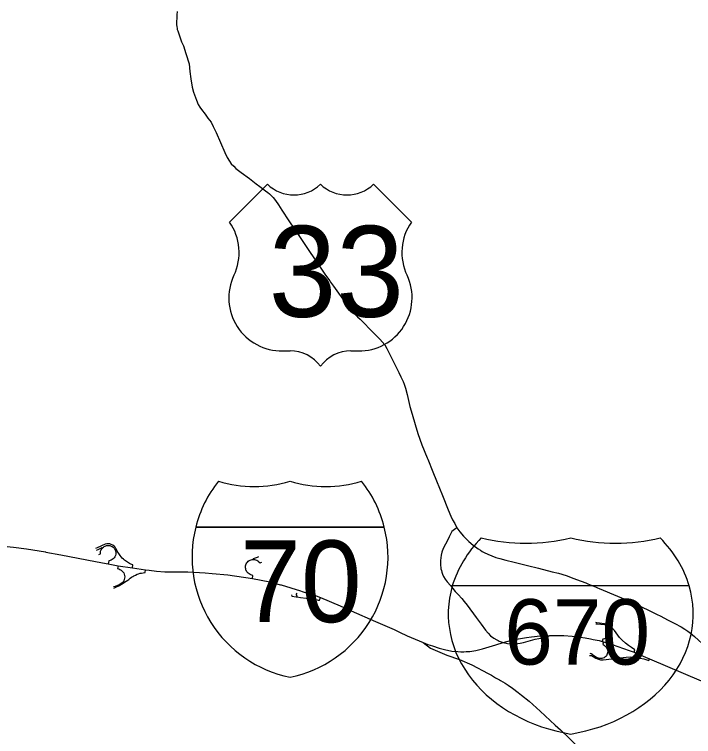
# Model space of a CAD drawing. Extents: x 0 to 34, y 0 to 22.
# Drawn here: x 4.266 to 5.228, y 17.132 to 18.155 of the extents above; entities that cross this region are included whole.
import ezdxf

# ---------------------------------------------------------------- set-up
doc = ezdxf.new("R2010")
doc.units = 0
for name, color, linetype in [('GM_X_Interchange_Ramps', 7, 'Continuous'), ('GM_X_Interstate_Route', 7, 'Continuous'), ('GM_X_Interstate_Shield', 7, 'Continuous'), ('GM_X_US_Route', 7, 'Continuous'), ('GM_X_US_Shield', 7, 'Continuous')]:
    doc.layers.add(name, color=color, linetype=linetype)

msp = doc.modelspace()

# ---------------------------------------------------------------- linework, layer by layer
at = {"layer": 'GM_X_Interchange_Ramps'}
for points in [[(4.4333, 17.3713), (4.434, 17.3754), (4.431, 17.3767), (4.4293, 17.3776), (4.4277, 17.3784), (4.4264, 17.3792), (4.4249, 17.3802), (4.4235, 17.3811), (4.4219, 17.3824), (4.4204, 17.3837), (4.4188, 17.3852), (4.4173, 17.3868), (4.4157, 17.3888), (4.4147, 17.3901), (4.4138, 17.3915), (4.4127, 17.3933), (4.4117, 17.395), (4.411, 17.3964), (4.4099, 17.3988), (4.4087, 17.4006), (4.4072, 17.4021), (4.4055, 17.4034), (4.4031, 17.4046), (4.401, 17.4052), (4.399, 17.4054), (4.3968, 17.4053), (4.3945, 17.4048), (4.3832, 17.3998), (4.3811, 17.3988)], [(4.3825, 17.3964), (4.3846, 17.3975), (4.3904, 17.4001), (4.3907, 17.3995)], [(4.3856, 17.3901), (4.3879, 17.3913), (4.3879, 17.3931), (4.3882, 17.3949), (4.389, 17.397), (4.3898, 17.3984), (4.3907, 17.3995), (4.3921, 17.4006), (4.3933, 17.4016), (4.3945, 17.4022), (4.3964, 17.4028), (4.3986, 17.4031), (4.401, 17.4029), (4.4029, 17.4022), (4.4044, 17.4015), (4.4059, 17.4004), (4.4072, 17.3991), (4.4084, 17.3972), (4.4092, 17.3952), (4.4096, 17.3932), (4.4096, 17.3909), (4.4091, 17.3888), (4.4084, 17.387), (4.4072, 17.3853), (4.4059, 17.3839), (4.4045, 17.3829), (4.403, 17.3821), (4.4015, 17.3816), (4.3996, 17.3813), (4.3989, 17.3768)], [(4.6044, 17.3832), (4.6045, 17.3844), (4.6103, 17.3866), (4.6123, 17.3875)], [(4.6031, 17.3561), (4.6037, 17.3606), (4.6024, 17.361), (4.6011, 17.3615), (4.5999, 17.362), (4.5984, 17.3628), (4.5973, 17.3636), (4.5963, 17.3645), (4.5953, 17.3657), (4.5946, 17.367), (4.594, 17.3682), (4.5936, 17.3697), (4.5934, 17.3711), (4.5933, 17.3726), (4.5935, 17.374), (4.5939, 17.3756), (4.5945, 17.377), (4.5953, 17.3784), (4.5961, 17.3795), (4.5972, 17.3806), (4.5985, 17.3815), (4.5999, 17.3822), (4.6015, 17.3828), (4.603, 17.3831), (4.6044, 17.3832), (4.6061, 17.383), (4.6076, 17.3827), (4.6092, 17.3821), (4.6106, 17.3812), (4.6118, 17.3803), (4.614, 17.3782), (4.6163, 17.3792)], [(4.4129, 17.3743), (4.4122, 17.3703), (4.414, 17.3697), (4.4156, 17.3691), (4.4172, 17.3682), (4.4184, 17.3673), (4.4197, 17.3659), (4.4209, 17.3641), (4.4216, 17.3624), (4.4221, 17.3604), (4.4223, 17.3587), (4.4221, 17.3567), (4.4216, 17.3549), (4.4209, 17.3531), (4.4199, 17.3516), (4.4187, 17.3502), (4.4172, 17.3492), (4.4153, 17.3479), (4.4086, 17.3451), (4.4064, 17.3442)], [(4.4071, 17.3427), (4.4087, 17.3435), (4.4148, 17.3464), (4.4179, 17.3484), (4.4202, 17.3497), (4.4221, 17.3508), (4.4244, 17.3523), (4.4265, 17.3537), (4.4282, 17.3549), (4.43, 17.3565), (4.4319, 17.3579), (4.4336, 17.359), (4.4354, 17.3601), (4.4374, 17.3611), (4.4399, 17.3622), (4.442, 17.363), (4.4441, 17.3636), (4.4462, 17.364), (4.4485, 17.3644), (4.4512, 17.3648), (4.4517, 17.3686)], [(4.6659, 17.3354), (4.6652, 17.3342), (4.6652, 17.3327), (4.6654, 17.3324), (4.6656, 17.332), (4.6659, 17.3317), (4.6662, 17.3314), (4.6661, 17.3303)], [(4.6585, 17.333), (4.6591, 17.3311), (4.665, 17.3304), (4.6661, 17.3303), (4.6713, 17.3293), (4.6793, 17.3284), (4.6815, 17.328), (4.6835, 17.3277), (4.6859, 17.3274), (4.688, 17.327), (4.6902, 17.3267), (4.6925, 17.3263), (4.6947, 17.326), (4.6964, 17.3257), (4.698, 17.3254), (4.6995, 17.3294)], [(5.0893, 17.2922), (5.0913, 17.2919), (5.1017, 17.291), (5.1034, 17.2908), (5.105, 17.2903), (5.1066, 17.2895), (5.108, 17.2884), (5.1091, 17.2872), (5.1099, 17.286), (5.1106, 17.2847), (5.111, 17.2831), (5.1113, 17.2814), (5.1112, 17.2801), (5.111, 17.2786), (5.1105, 17.2772), (5.1099, 17.276), (5.1092, 17.2748), (5.1082, 17.2737), (5.107, 17.2727), (5.1056, 17.2719), (5.1045, 17.2715), (5.1032, 17.2711), (5.102, 17.2708), (5.0993, 17.2704), (5.0984, 17.2671)], [(5.1437, 17.2517), (5.1449, 17.2552), (5.1399, 17.2585), (5.1356, 17.2614), (5.1317, 17.2646), (5.1268, 17.2691), (5.1231, 17.2727), (5.1158, 17.2824), (5.1114, 17.2878), (5.1078, 17.2903), (5.1046, 17.2917), (5.1019, 17.2922), (5.091, 17.2936), (5.0895, 17.2938)], [(5.1004, 17.2666), (5.0995, 17.263), (5.102, 17.2613), (5.103, 17.26), (5.104, 17.2591), (5.1048, 17.2579), (5.1056, 17.2565), (5.106, 17.2553), (5.1063, 17.254), (5.1064, 17.2526), (5.1062, 17.2509), (5.1058, 17.2493), (5.1053, 17.2482), (5.1046, 17.2469), (5.1036, 17.2458), (5.1024, 17.2447), (5.1011, 17.2439), (5.0996, 17.2433), (5.098, 17.2429), (5.0962, 17.2428), (5.0947, 17.243), (5.0934, 17.2433), (5.0907, 17.2443), (5.0869, 17.2466), (5.0851, 17.248), (5.0831, 17.2496), (5.0813, 17.2501)], [(5.0807, 17.2474), (5.0834, 17.2471), (5.0897, 17.2432), (5.0932, 17.2418), (5.0963, 17.2411), (5.1, 17.2411), (5.1326, 17.2447), (5.1381, 17.2451), (5.143, 17.2448), (5.1463, 17.2445), (5.1521, 17.2435), (5.1574, 17.2423), (5.1648, 17.2402), (5.1656, 17.2425)]]:
    msp.add_lwpolyline(points, dxfattribs=at)
at = {"layer": 'GM_X_Interstate_Route'}
for points in [[(4.2367, 17.4035), (4.2649, 17.4008), (4.2832, 17.3983), (4.3099, 17.3938), (4.3106, 17.3937)], [(4.3106, 17.3937), (4.3316, 17.3896), (4.3688, 17.3828), (4.3909, 17.3783)], [(4.3909, 17.3783), (4.3989, 17.3768), (4.4129, 17.3743), (4.4333, 17.3713), (4.4517, 17.3686), (4.457, 17.3678)], [(4.457, 17.3678), (4.4672, 17.3664), (4.4791, 17.3655), (4.5116, 17.3656), (4.5364, 17.3644), (4.546, 17.3635), (4.5682, 17.3615), (4.6031, 17.3561), (4.6276, 17.3513)], [(4.6276, 17.3513), (4.629, 17.351), (4.6321, 17.3502)], [(4.6321, 17.3502), (4.6431, 17.3474)], [(4.6431, 17.3474), (4.6437, 17.3473), (4.6576, 17.3429), (4.6711, 17.3387), (4.6738, 17.3379), (4.6765, 17.337), (4.6822, 17.3352)], [(4.6822, 17.3352), (4.691, 17.3325), (4.6995, 17.3294), (4.7274, 17.3177), (4.7432, 17.3104), (4.7773, 17.2952), (4.8038, 17.2838)], [(4.8038, 17.2838), (4.8117, 17.2804), (4.8221, 17.2751), (4.8335, 17.2702), (4.845, 17.2655)], [(4.9794, 17.2706), (4.9798, 17.2707), (4.9911, 17.2726), (4.9983, 17.2736), (5.0105, 17.2749), (5.0242, 17.2756)], [(5.0242, 17.2756), (5.0442, 17.2753), (5.0559, 17.2745), (5.0673, 17.273), (5.0743, 17.272), (5.0818, 17.2708), (5.0856, 17.2699), (5.0941, 17.2682), (5.0984, 17.2671), (5.1004, 17.2666), (5.1096, 17.2637)], [(4.845, 17.2655), (4.8556, 17.2577), (4.8783, 17.2475), (4.8963, 17.2417), (4.8965, 17.2416)], [(4.845, 17.2655), (4.8518, 17.2629), (4.8582, 17.2607), (4.8677, 17.2575), (4.875, 17.2555), (4.8855, 17.2535), (4.894, 17.2528), (4.8982, 17.2526), (4.9027, 17.2526), (4.9059, 17.2527), (4.9111, 17.253), (4.9196, 17.2544), (4.9291, 17.2565), (4.9386, 17.2595)], [(4.9386, 17.2595), (4.9477, 17.2623), (4.9581, 17.2657), (4.9707, 17.2687), (4.9794, 17.2706)], [(5.1096, 17.2637), (5.1127, 17.2628), (5.1368, 17.2544), (5.1437, 17.2517), (5.1534, 17.2477), (5.1599, 17.2449), (5.1656, 17.2425), (5.2387, 17.2115), (5.2547, 17.2046), (5.2604, 17.2023), (5.2647, 17.2007), (5.2707, 17.1988), (5.2748, 17.1978), (5.2794, 17.197), (5.284, 17.1964), (5.288, 17.1962), (5.2938, 17.1962), (5.2988, 17.1966), (5.3022, 17.197), (5.3055, 17.1976), (5.3092, 17.1985), (5.3118, 17.1992), (5.3154, 17.2004)], [(4.8965, 17.2416), (4.914, 17.2341), (4.9372, 17.2219), (4.9417, 17.2192)], [(4.9417, 17.2192), (4.9476, 17.2157), (4.9529, 17.2128), (4.9543, 17.212)], [(4.9543, 17.212), (4.961, 17.208), (4.9655, 17.2052), (4.9716, 17.2007), (4.9794, 17.195), (4.9844, 17.1908), (4.9949, 17.1825), (5.0105, 17.1683), (5.0318, 17.1484), (5.0395, 17.1419), (5.052, 17.1298), (5.0641, 17.1176), (5.0746, 17.1074), (5.0907, 17.0882), (5.0972, 17.0802), (5.104, 17.0714)]]:
    msp.add_lwpolyline(points, dxfattribs=at)
at = {"layer": 'GM_X_Interstate_Shield'}
for p, q in [((4.5229, 17.4289), (4.7899, 17.4289)), ((4.7899, 17.4289), (4.5229, 17.4289)), ((4.7899, 17.4289), (4.5229, 17.4289)), ((5.2218, 17.3457), (4.8862, 17.3457)), ((5.2218, 17.3457), (4.8862, 17.3457))]:
    msp.add_line(p, q, dxfattribs=at)
for centre, start, end in [((4.6911, 17.3864), 141.669, 165.8066), ((4.6057, 17.66), 253.0091, 286.9909), ((4.7071, 17.66), 253.0091, 286.9909), ((4.6217, 17.3864), 14.1934, 38.331), ((4.6911, 17.3864), 165.8066, 258.463), ((4.6217, 17.3864), 281.537, 14.1934)]:
    msp.add_arc(centre, 0.1735, start, end, dxfattribs=at)
for centre, start_param, end_param in [((5.0974, 17.306), 2.47259, 2.911027), ((4.9906, 17.5796), 4.415841, 5.008937), ((5.1174, 17.5796), 4.415841, 5.008937), ((5.0106, 17.306), 0.230566, 0.669003), ((5.0974, 17.306), 2.911027, 4.511031), ((5.0106, 17.306), 4.913747, 6.513751)]:
    msp.add_ellipse(centre, major_axis=(0.2169, 0), ratio=0.8, start_param=start_param, end_param=end_param, dxfattribs=at)
at = {"layer": 'GM_X_US_Route'}
for points in [[(4.4966, 18.1594), (4.4962, 18.1544), (4.4956, 18.1406), (4.496, 18.1379), (4.4964, 18.1351), (4.4968, 18.1336), (4.4973, 18.1319), (4.5027, 18.1165), (4.5054, 18.1105), (4.5088, 18.1), (4.5134, 18.0852), (4.5146, 18.0744), (4.5158, 18.0639), (4.5178, 18.052), (4.5199, 18.0451), (4.5238, 18.0338), (4.5265, 18.0274), (4.5286, 18.0238), (4.5309, 18.0203), (4.5361, 18.0137), (4.5401, 18.0084), (4.5445, 18.0024), (4.5477, 17.9964), (4.5516, 17.9881), (4.5641, 17.9596), (4.5675, 17.9523), (4.5705, 17.9473), (4.5732, 17.9437), (4.5766, 17.9403), (4.5799, 17.9369), (4.5871, 17.9313), (4.5989, 17.9226), (4.6086, 17.9153), (4.6137, 17.9114), (4.6219, 17.9052), (4.6252, 17.9027)], [(4.6252, 17.9027), (4.6272, 17.9012), (4.6299, 17.8987), (4.6326, 17.8958), (4.636, 17.8916), (4.6401, 17.8855), (4.6448, 17.8781)], [(4.6448, 17.8781), (4.6548, 17.8626), (4.6697, 17.8406), (4.6832, 17.8208)], [(4.6832, 17.8208), (4.6842, 17.8193), (4.6952, 17.8029), (4.7065, 17.786)], [(4.7065, 17.786), (4.7127, 17.7776), (4.7137, 17.7761)], [(4.7137, 17.7761), (4.718, 17.7701), (4.725, 17.7603), (4.7324, 17.7501), (4.7353, 17.7462)], [(4.7353, 17.7462), (4.7387, 17.7415), (4.7464, 17.7327), (4.752, 17.7269), (4.7557, 17.7234), (4.7591, 17.72), (4.7718, 17.7072), (4.7837, 17.6951), (4.7908, 17.6872), (4.7934, 17.6822), (4.7994, 17.6707), (4.8058, 17.6573), (4.8101, 17.6487), (4.8104, 17.6482)], [(4.8104, 17.6482), (4.8135, 17.642), (4.8166, 17.6354), (4.8183, 17.6313), (4.82, 17.6259), (4.8223, 17.6168), (4.8263, 17.5997), (4.8292, 17.5888), (4.8335, 17.5742), (4.8376, 17.5616), (4.8432, 17.5455), (4.8507, 17.5271), (4.8514, 17.5253)], [(4.8514, 17.5253), (4.8585, 17.5075), (4.864, 17.4944), (4.8723, 17.4738), (4.8806, 17.4534), (4.8843, 17.4445), (4.8867, 17.4395), (4.8896, 17.434), (4.8929, 17.4278)], [(4.8929, 17.4278), (4.8894, 17.4255), (4.8858, 17.4226), (4.8843, 17.4201), (4.8819, 17.4153)], [(4.8929, 17.4278), (4.897, 17.4224), (4.9021, 17.4163), (4.9097, 17.4085), (4.9157, 17.4034), (4.9227, 17.3983), (4.926, 17.3962), (4.9286, 17.3946), (4.9313, 17.3931), (4.9364, 17.3905), (4.9423, 17.3881), (4.9477, 17.3862), (4.9535, 17.3844), (4.9619, 17.3822), (4.9739, 17.3793), (4.9927, 17.3747), (5.0084, 17.3707), (5.0278, 17.3658), (5.0367, 17.3637), (5.0474, 17.3603), (5.0583, 17.3563), (5.0621, 17.3548), (5.0752, 17.3499), (5.0784, 17.3486), (5.09, 17.3438), (5.092, 17.343)], [(4.8819, 17.4153), (4.8798, 17.4111), (4.8735, 17.3985), (4.8716, 17.3935), (4.8704, 17.3893), (4.8698, 17.3853), (4.8693, 17.3817), (4.8693, 17.3776), (4.8695, 17.3746), (4.8699, 17.3719), (4.8702, 17.3697), (4.8708, 17.3674), (4.8715, 17.365), (4.8726, 17.3622), (4.874, 17.3592), (4.8761, 17.3554), (4.8789, 17.3515), (4.8836, 17.3462), (4.8905, 17.338), (4.8947, 17.3334), (4.8999, 17.3277), (4.9032, 17.3237)], [(5.092, 17.343), (5.0941, 17.3422)], [(5.0941, 17.3422), (5.1202, 17.3313), (5.1337, 17.3255), (5.1514, 17.3173), (5.1677, 17.3095), (5.1755, 17.3056)], [(4.9032, 17.3237), (4.9074, 17.3186), (4.92, 17.301), (4.9269, 17.2916), (4.9334, 17.2829), (4.9371, 17.2786), (4.9405, 17.2751), (4.9449, 17.2719), (4.9493, 17.2694), (4.951, 17.2684), (4.9528, 17.2676), (4.9581, 17.2657), (4.9642, 17.2642), (4.9692, 17.2636), (4.9723, 17.2636), (4.9759, 17.2637), (4.9823, 17.2647), (4.9873, 17.2657), (4.997, 17.2685), (5.0036, 17.2702), (5.0089, 17.2711), (5.0167, 17.2718), (5.0242, 17.2756)], [(5.1755, 17.3056), (5.1814, 17.3027), (5.1908, 17.2978), (5.2014, 17.2924), (5.2104, 17.2876), (5.2157, 17.2846), (5.22, 17.2816), (5.2234, 17.279), (5.2292, 17.2742), (5.2348, 17.2691), (5.2403, 17.2643), (5.2403, 17.2643)]]:
    msp.add_lwpolyline(points, dxfattribs=at)
at = {"layer": 'GM_X_US_Shield'}
for p, q in [((4.6244, 17.9147), (4.5707, 17.8611)), ((4.8284, 17.8611), (4.7747, 17.9147)), ((4.6459, 17.6785), (4.6566, 17.6785)), ((4.7425, 17.6785), (4.7532, 17.6785))]:
    msp.add_line(p, q, dxfattribs=at)
for centre, radius, start, end in [((4.662, 17.9531), 0.0537, 225.573, 314.427), ((4.7371, 17.9531), 0.0537, 225.573, 314.427), ((4.5091, 17.8179), 0.0752, 334.5471, 35.0009), ((4.89, 17.8179), 0.0752, 144.9991, 205.4529), ((4.645, 17.7537), 0.0752, 154.8319, 270.6383), ((4.7541, 17.7537), 0.0752, 269.3617, 25.1681), ((4.6566, 17.6248), 0.0537, 36.8699, 90), ((4.7425, 17.6248), 0.0537, 90, 143.1301)]:
    msp.add_arc(centre, radius, start, end, dxfattribs=at)

# ---------------------------------------------------------------- texts
at = {"layer": 'GM_X_Interstate_Shield'}
for s, height, p in [('70', 0.11569, (4.5858, 17.2944)), ('670', 0.09255, (4.9599, 17.2343))]:
    msp.add_text(s, height=height, dxfattribs=at).set_placement(p)
at = {"layer": 'GM_X_US_Shield'}
msp.add_text('33', height=0.12885, dxfattribs=at).set_placement((4.6262, 17.7268))

doc.saveas('drawing.dxf')
